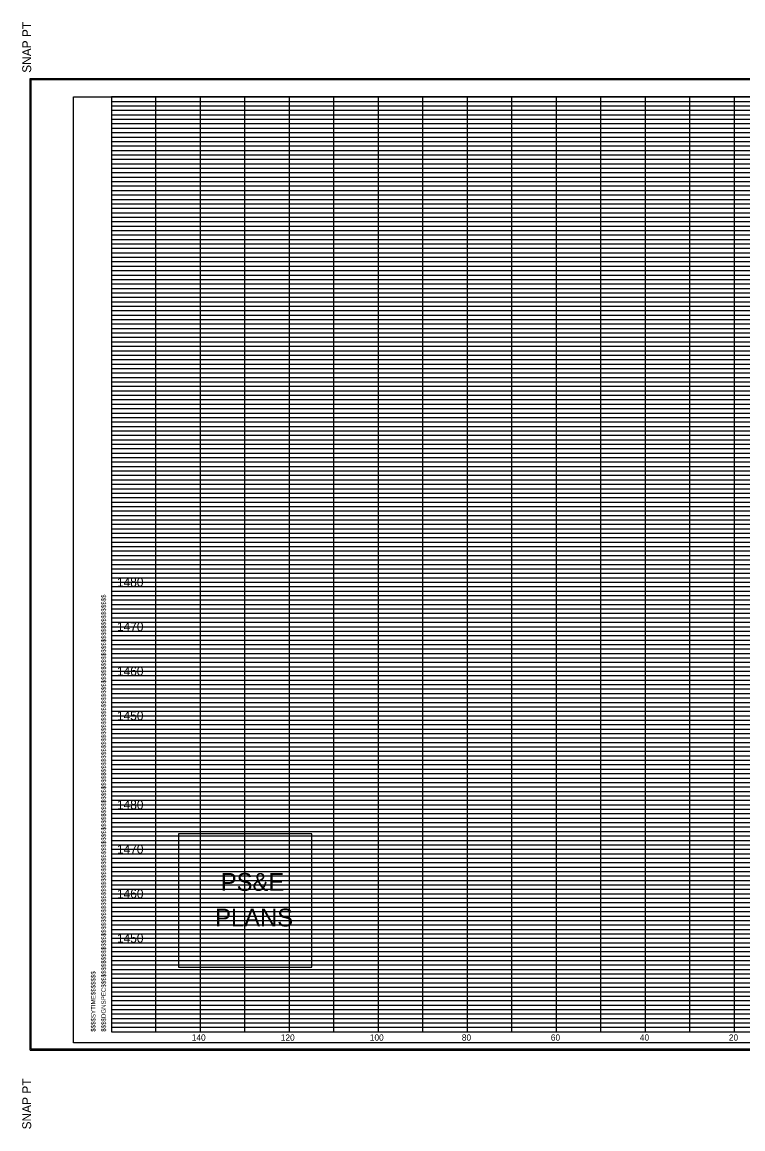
# Model space of a CAD drawing. Extents: x 980 to 1324, y 978 to 1227.
# Drawn here: x 979.9 to 1141.9, y 978.2 to 1226.8 of the extents above; entities that cross this region are included whole.
import ezdxf

# ---------------------------------------------------------------- set-up
doc = ezdxf.new("R2010")
doc.units = 0
for name, color, linetype in [('DESIGN - SHEET - Corner Text', 7, 'Continuous'), ('DESIGN - SHEET - Light Grid', 7, 'Continuous'), ('DESIGN - SHEET - Linework', 7, 'Continuous'), ('DESIGN - SHEET - Plot Shape', 7, 'Continuous'), ('DESIGN - TYPICAL - Finished Grade and Subgrade', 7, 'Continuous')]:
    doc.layers.add(name, color=color, linetype=linetype)

# ---------------------------------------------------------------- blocks, each defined once
blk = doc.blocks.new('XSTSHT')
at = {"layer": 'DESIGN - SHEET - Light Grid'}
for p, q in [((0, 20.9), (8, 20.9)), ((8, 20.9), (16, 20.9)), ((0, 20.8), (8, 20.8)), ((0, 20.7), (8, 20.7)), ((8, 20.8), (16, 20.8)), ((8, 20.7), (16, 20.7)), ((0, 20.6), (8, 20.6)), ((0, 20.5), (8, 20.5)), ((0, 20.4), (8, 20.4)), ((8, 20.6), (16, 20.6)), ((8, 20.5), (16, 20.5)), ((8, 20.4), (16, 20.4)), ((0, 20.3), (8, 20.3)), ((0, 20.2), (8, 20.2)), ((8, 20.3), (16, 20.3)), ((8, 20.2), (16, 20.2)), ((0, 20.1), (8, 20.1)), ((0, 19.9), (8, 19.9)), ((8, 20.1), (16, 20.1)), ((8, 19.9), (16, 19.9)), ((0, 19.8), (8, 19.8)), ((0, 19.7), (8, 19.7)), ((8, 19.8), (16, 19.8)), ((8, 19.7), (16, 19.7)), ((0, 19.6), (8, 19.6)), ((0, 19.5), (8, 19.5)), ((0, 19.4), (8, 19.4)), ((8, 19.6), (16, 19.6)), ((8, 19.5), (16, 19.5)), ((8, 19.4), (16, 19.4)), ((0, 19.3), (8, 19.3)), ((0, 19.2), (8, 19.2)), ((8, 19.3), (16, 19.3)), ((8, 19.2), (16, 19.2)), ((0, 19.1), (8, 19.1)), ((0, 18.9), (8, 18.9)), ((8, 19.1), (16, 19.1)), ((8, 18.9), (16, 18.9)), ((0, 18.8), (8, 18.8)), ((0, 18.7), (8, 18.7)), ((8, 18.8), (16, 18.8)), ((8, 18.7), (16, 18.7)), ((0, 18.6), (8, 18.6)), ((0, 18.5), (8, 18.5)), ((0, 18.4), (8, 18.4)), ((8, 18.6), (16, 18.6)), ((8, 18.5), (16, 18.5)), ((8, 18.4), (16, 18.4)), ((0, 18.3), (8, 18.3)), ((0, 18.2), (8, 18.2)), ((8, 18.3), (16, 18.3)), ((8, 18.2), (16, 18.2)), ((0, 18.1), (8, 18.1)), ((8, 18.1), (16, 18.1)), ((0, 17.9), (8, 17.9)), ((0, 17.8), (8, 17.8)), ((0, 17.7), (8, 17.7)), ((8, 17.9), (16, 17.9)), ((8, 17.8), (16, 17.8)), ((8, 17.7), (16, 17.7)), ((0, 17.6), (8, 17.6)), ((0, 17.5), (8, 17.5)), ((8, 17.6), (16, 17.6)), ((8, 17.5), (16, 17.5)), ((0, 17.4), (8, 17.4)), ((0, 17.3), (8, 17.3)), ((0, 17.2), (8, 17.2)), ((8, 17.4), (16, 17.4)), ((8, 17.3), (16, 17.3)), ((8, 17.2), (16, 17.2)), ((0, 17.1), (8, 17.1)), ((8, 17.1), (16, 17.1)), ((0, 16.9), (8, 16.9)), ((0, 16.8), (8, 16.8)), ((0, 16.7), (8, 16.7)), ((8, 16.9), (16, 16.9)), ((8, 16.8), (16, 16.8)), ((8, 16.7), (16, 16.7)), ((0, 16.6), (8, 16.6)), ((0, 16.5), (8, 16.5)), ((8, 16.6), (16, 16.6)), ((8, 16.5), (16, 16.5)), ((0, 16.4), (8, 16.4)), ((0, 16.3), (8, 16.3)), ((0, 16.2), (8, 16.2)), ((8, 16.4), (16, 16.4)), ((8, 16.3), (16, 16.3)), ((8, 16.2), (16, 16.2)), ((0, 16.1), (8, 16.1)), ((8, 16.1), (16, 16.1)), ((0, 15.9), (8, 15.9)), ((0, 15.8), (8, 15.8)), ((0, 15.7), (8, 15.7)), ((8, 15.9), (16, 15.9)), ((8, 15.8), (16, 15.8)), ((8, 15.7), (16, 15.7)), ((0, 15.6), (8, 15.6)), ((0, 15.5), (8, 15.5)), ((8, 15.6), (16, 15.6)), ((8, 15.5), (16, 15.5)), ((0, 15.4), (8, 15.4)), ((0, 15.3), (8, 15.3)), ((0, 15.2), (8, 15.2)), ((8, 15.4), (16, 15.4)), ((8, 15.3), (16, 15.3)), ((8, 15.2), (16, 15.2)), ((0, 15.1), (8, 15.1)), ((8, 15.1), (16, 15.1)), ((0, 14.9), (8, 14.9)), ((0, 14.8), (8, 14.8)), ((0, 14.7), (8, 14.7)), ((8, 14.9), (16, 14.9)), ((8, 14.8), (16, 14.8)), ((8, 14.7), (16, 14.7)), ((0, 14.6), (8, 14.6)), ((0, 14.5), (8, 14.5)), ((8, 14.6), (16, 14.6)), ((8, 14.5), (16, 14.5)), ((0, 14.4), (8, 14.4)), ((0, 14.3), (8, 14.3)), ((0, 14.2), (8, 14.2)), ((8, 14.4), (16, 14.4)), ((8, 14.3), (16, 14.3)), ((8, 14.2), (16, 14.2)), ((0, 14.1), (8, 14.1)), ((8, 14.1), (16, 14.1)), ((0, 13.9), (8, 13.9)), ((0, 13.8), (8, 13.8)), ((0, 13.7), (8, 13.7)), ((8, 13.9), (16, 13.9)), ((8, 13.8), (16, 13.8)), ((8, 13.7), (16, 13.7)), ((0, 13.6), (8, 13.6)), ((0, 13.5), (8, 13.5)), ((8, 13.6), (16, 13.6)), ((8, 13.5), (16, 13.5)), ((0, 13.4), (8, 13.4)), ((0, 13.3), (8, 13.3)), ((0, 13.2), (8, 13.2)), ((8, 13.4), (16, 13.4)), ((8, 13.3), (16, 13.3)), ((8, 13.2), (16, 13.2)), ((0, 13.1), (8, 13.1)), ((8, 13.1), (16, 13.1)), ((0, 12.9), (8, 12.9)), ((0, 12.8), (8, 12.8)), ((0, 12.7), (8, 12.7)), ((8, 12.9), (16, 12.9)), ((8, 12.8), (16, 12.8)), ((8, 12.7), (16, 12.7)), ((0, 12.6), (8, 12.6)), ((0, 12.5), (8, 12.5)), ((8, 12.6), (16, 12.6)), ((8, 12.5), (16, 12.5)), ((0, 12.4), (8, 12.4)), ((0, 12.3), (8, 12.3)), ((0, 12.2), (8, 12.2)), ((8, 12.4), (16, 12.4)), ((8, 12.3), (16, 12.3)), ((8, 12.2), (16, 12.2)), ((0, 12.1), (8, 12.1)), ((8, 12.1), (16, 12.1)), ((0, 11.9), (8, 11.9)), ((0, 11.8), (8, 11.8)), ((0, 11.7), (8, 11.7)), ((8, 11.9), (16, 11.9)), ((8, 11.8), (16, 11.8)), ((8, 11.7), (16, 11.7)), ((0, 11.6), (8, 11.6)), ((0, 11.5), (8, 11.5)), ((8, 11.6), (16, 11.6)), ((8, 11.5), (16, 11.5)), ((0, 11.4), (8, 11.4)), ((0, 11.3), (8, 11.3)), ((0, 11.2), (8, 11.2)), ((8, 11.4), (16, 11.4)), ((8, 11.3), (16, 11.3)), ((8, 11.2), (16, 11.2)), ((0, 11.1), (8, 11.1)), ((8, 11.1), (16, 11.1)), ((0, 10.9), (8, 10.9)), ((0, 10.8), (8, 10.8)), ((0, 10.7), (8, 10.7)), ((8, 10.9), (16, 10.9)), ((8, 10.8), (16, 10.8)), ((8, 10.7), (16, 10.7)), ((0, 10.6), (8, 10.6)), ((0, 10.5), (8, 10.5)), ((8, 10.6), (16, 10.6)), ((8, 10.5), (16, 10.5)), ((0, 10.4), (8, 10.4)), ((0, 10.3), (8, 10.3)), ((0, 10.2), (8, 10.2)), ((8, 10.4), (16, 10.4)), ((8, 10.3), (16, 10.3)), ((8, 10.2), (16, 10.2)), ((0, 10.1), (8, 10.1)), ((8, 10.1), (16, 10.1)), ((0, 9.9), (8, 9.9)), ((0, 9.8), (8, 9.8)), ((0, 9.7), (8, 9.7)), ((8, 9.9), (16, 9.9)), ((8, 9.8), (16, 9.8)), ((8, 9.7), (16, 9.7)), ((0, 9.6), (8, 9.6)), ((0, 9.5), (8, 9.5)), ((8, 9.6), (16, 9.6)), ((8, 9.5), (16, 9.5)), ((0, 9.4), (8, 9.4)), ((0, 9.3), (8, 9.3)), ((0, 9.2), (8, 9.2)), ((8, 9.4), (16, 9.4)), ((8, 9.3), (16, 9.3)), ((8, 9.2), (16, 9.2)), ((0, 9.1), (8, 9.1)), ((8, 9.1), (16, 9.1)), ((0, 8.9), (8, 8.9)), ((0, 8.8), (8, 8.8)), ((8, 8.9), (16, 8.9)), ((8, 8.8), (16, 8.8)), ((0, 8.7), (8, 8.7)), ((0, 8.6), (8, 8.6)), ((0, 8.5), (8, 8.5)), ((8, 8.7), (16, 8.7)), ((8, 8.6), (16, 8.6)), ((8, 8.5), (16, 8.5)), ((0, 8.4), (8, 8.4)), ((0, 8.3), (8, 8.3)), ((8, 8.4), (16, 8.4)), ((8, 8.3), (16, 8.3)), ((0, 8.2), (8, 8.2)), ((0, 8.1), (8, 8.1)), ((8, 8.2), (16, 8.2)), ((8, 8.1), (16, 8.1)), ((0, 7.9), (8, 7.9)), ((0, 7.8), (8, 7.8)), ((8, 7.9), (16, 7.9)), ((8, 7.8), (16, 7.8)), ((0, 7.7), (8, 7.7)), ((0, 7.6), (8, 7.6)), ((0, 7.5), (8, 7.5)), ((8, 7.7), (16, 7.7)), ((8, 7.6), (16, 7.6)), ((8, 7.5), (16, 7.5)), ((0, 7.4), (8, 7.4)), ((0, 7.3), (8, 7.3)), ((8, 7.4), (16, 7.4)), ((8, 7.3), (16, 7.3)), ((0, 7.2), (8, 7.2)), ((0, 7.1), (8, 7.1)), ((8, 7.2), (16, 7.2)), ((8, 7.1), (16, 7.1)), ((0, 6.9), (8, 6.9)), ((0, 6.8), (8, 6.8)), ((8, 6.9), (16, 6.9)), ((8, 6.8), (16, 6.8)), ((0, 6.7), (8, 6.7)), ((0, 6.6), (8, 6.6)), ((0, 6.5), (8, 6.5)), ((8, 6.7), (16, 6.7)), ((8, 6.6), (16, 6.6)), ((8, 6.5), (16, 6.5)), ((0, 6.4), (8, 6.4)), ((0, 6.3), (8, 6.3)), ((8, 6.4), (16, 6.4)), ((8, 6.3), (16, 6.3)), ((0, 6.2), (8, 6.2)), ((0, 6.1), (8, 6.1)), ((8, 6.2), (16, 6.2)), ((8, 6.1), (16, 6.1)), ((0, 5.9), (8, 5.9)), ((0, 5.8), (8, 5.8)), ((8, 5.9), (16, 5.9)), ((8, 5.8), (16, 5.8)), ((0, 5.7), (8, 5.7)), ((0, 5.6), (8, 5.6)), ((0, 5.5), (8, 5.5)), ((8, 5.7), (16, 5.7)), ((8, 5.6), (16, 5.6)), ((8, 5.5), (16, 5.5)), ((0, 5.4), (8, 5.4)), ((0, 5.3), (8, 5.3)), ((8, 5.4), (16, 5.4)), ((8, 5.3), (16, 5.3)), ((0, 5.2), (8, 5.2)), ((0, 5.1), (8, 5.1)), ((8, 5.2), (16, 5.2)), ((8, 5.1), (16, 5.1)), ((0, 4.9), (8, 4.9)), ((0, 4.8), (8, 4.8)), ((8, 4.9), (16, 4.9)), ((8, 4.8), (16, 4.8)), ((0, 4.7), (8, 4.7)), ((0, 4.6), (8, 4.6)), ((0, 4.5), (8, 4.5)), ((8, 4.7), (16, 4.7)), ((8, 4.6), (16, 4.6)), ((8, 4.5), (16, 4.5)), ((0, 4.4), (8, 4.4)), ((0, 4.3), (8, 4.3)), ((8, 4.4), (16, 4.4)), ((8, 4.3), (16, 4.3)), ((0, 4.2), (8, 4.2)), ((0, 4.1), (8, 4.1)), ((8, 4.2), (16, 4.2)), ((8, 4.1), (16, 4.1)), ((0, 3.9), (8, 3.9)), ((0, 3.8), (8, 3.8)), ((8, 3.9), (16, 3.9)), ((8, 3.8), (16, 3.8)), ((0, 3.7), (8, 3.7)), ((0, 3.6), (8, 3.6)), ((0, 3.5), (8, 3.5)), ((8, 3.7), (16, 3.7)), ((8, 3.6), (16, 3.6)), ((8, 3.5), (16, 3.5)), ((0, 3.4), (8, 3.4)), ((0, 3.3), (8, 3.3)), ((8, 3.4), (16, 3.4)), ((8, 3.3), (16, 3.3)), ((0, 3.2), (8, 3.2)), ((0, 3.1), (8, 3.1)), ((8, 3.2), (16, 3.2)), ((8, 3.1), (16, 3.1)), ((0, 2.9), (8, 2.9)), ((0, 2.8), (8, 2.8)), ((8, 2.9), (16, 2.9)), ((8, 2.8), (16, 2.8)), ((0, 2.7), (8, 2.7)), ((0, 2.6), (8, 2.6)), ((0, 2.5), (8, 2.5)), ((8, 2.7), (16, 2.7)), ((8, 2.6), (16, 2.6)), ((8, 2.5), (16, 2.5)), ((0, 2.4), (8, 2.4)), ((0, 2.3), (8, 2.3)), ((8, 2.4), (16, 2.4)), ((8, 2.3), (16, 2.3)), ((0, 2.2), (8, 2.2)), ((0, 2.1), (8, 2.1)), ((8, 2.2), (16, 2.2)), ((8, 2.1), (16, 2.1)), ((0, 1.9), (8, 1.9)), ((0, 1.8), (8, 1.8)), ((8, 1.9), (16, 1.9)), ((8, 1.8), (16, 1.8)), ((0, 1.7), (8, 1.7)), ((0, 1.6), (8, 1.6)), ((0, 1.5), (8, 1.5)), ((8, 1.7), (16, 1.7)), ((8, 1.6), (16, 1.6)), ((8, 1.5), (16, 1.5)), ((0, 1.4), (8, 1.4)), ((0, 1.3), (8, 1.3)), ((8, 1.4), (16, 1.4)), ((8, 1.3), (16, 1.3)), ((0, 1.2), (8, 1.2)), ((0, 1.1), (8, 1.1)), ((8, 1.2), (16, 1.2)), ((8, 1.1), (16, 1.1)), ((0, 0.9), (8, 0.9)), ((0, 0.8), (8, 0.8)), ((8, 0.9), (16, 0.9)), ((8, 0.8), (16, 0.8)), ((0, 0.7), (8, 0.7)), ((0, 0.6), (8, 0.6)), ((0, 0.5), (8, 0.5)), ((8, 0.7), (16, 0.7)), ((8, 0.6), (16, 0.6)), ((8, 0.5), (16, 0.5)), ((0, 0.4), (8, 0.4)), ((0, 0.3), (8, 0.3)), ((8, 0.4), (16, 0.4)), ((8, 0.3), (16, 0.3)), ((0, 0.2), (8, 0.2)), ((0, 0.1), (8, 0.1)), ((8, 0.2), (16, 0.2)), ((8, 0.1), (16, 0.1))]:
    blk.add_line(p, q, dxfattribs=at)
at = {"layer": 'DESIGN - SHEET - Linework'}
for p, q in [((-1.823, -0.414), (-1.823, 21.414)), ((-1.823, 21.414), (32.217, 21.414)), ((1, 0), (1, 21)), ((2, 0), (2, 21)), ((3, 0), (3, 21)), ((4, 0), (4, 21)), ((5, 0), (5, 21)), ((6, 0), (6, 21)), ((7, 0), (7, 21)), ((8, 0), (8, 21)), ((9, 0), (9, 21)), ((10, 0), (10, 21)), ((11, 0), (11, 21)), ((12, 0), (12, 21)), ((13, 0), (13, 21)), ((14, 0), (14, 21)), ((0, 20), (28, 20)), ((0, 19), (32, 19)), ((0, 18), (32, 18)), ((0, 17), (32, 17)), ((0, 16), (32, 16)), ((0, 15), (32, 15)), ((0, 14), (32, 14)), ((0, 13), (32, 13)), ((0, 12), (32, 12)), ((0, 11), (32, 11)), ((0, 10), (32, 10)), ((0, 9), (32, 9)), ((0, 8), (32, 8)), ((0, 7), (32, 7)), ((0, 6), (32, 6)), ((0, 5), (32, 5)), ((0, 4), (32, 4)), ((0, 3), (32, 3)), ((0, 2), (32, 2)), ((0, 1), (32, 1)), ((-1.823, -0.414), (32.217, -0.414))]:
    blk.add_line(p, q, dxfattribs=at)
blk.add_lwpolyline([(0, 21), (0, 0), (32, 0), (32, 21), (0, 21)], dxfattribs=at)
at = {"layer": 'DESIGN - SHEET - Plot Shape'}
for points in [[(-1.803, 21.394), (32.197, 21.394), (32.197, -0.394), (-1.803, -0.394)], [(-0.85, 21), (32, 21), (32, -0.25), (-0.85, -0.25)]]:
    blk.add_lwpolyline(points, close=True, dxfattribs=at)
at = {"layer": 'DESIGN - SHEET - Corner Text'}
for s, height, p in [('  SNAP PT', 0.2, (-1.803, 21.394)), ('$$$$DGNSPEC$$$$$$$$$$$$$$$$$$$$$$$$$$$$$$$$$$$$$$$$$$$$$$$$$$$$$$$$$$$$$$$$$$$$$$$$$$$$$$$$$$$$$$$$$$$$$$$$$$$$$$$$$$$$$$$$$$$', 0.100002, (-0.126, 0)), ('$$$$SYTIME$$$$$$$', 0.1, (-0.358, 0)), ('SNAP PT  ', 0.2, (-1.803, -2.194))]:
    blk.add_text(s, height=height, rotation=90, dxfattribs=at).set_placement(p)

msp = doc.modelspace()

# ---------------------------------------------------------------- linework, layer by layer
at = {"layer": 'DESIGN - SHEET - Corner Text'}
msp.add_lwpolyline([(1015.05, 1044.49), (1015.05, 1014.49), (1045.05, 1014.49), (1045.05, 1044.49)], close=True, dxfattribs=at)

# ---------------------------------------------------------------- block references
at = {"layer": 'DESIGN - TYPICAL - Finished Grade and Subgrade', "xscale": 10, "yscale": 10}
msp.add_blockref('XSTSHT', (1000, 1000), dxfattribs=at)

# ---------------------------------------------------------------- texts
at = {"layer": 'DESIGN - SHEET - Corner Text'}
for s, height, p in [('1480', 2, (1001.25, 1100)), ('1470', 2, (1001.25, 1090)), ('1460', 2, (1001.25, 1080)), ('1450', 2, (1001.25, 1070)), ('1480', 2, (1001.25, 1050)), ('1470', 2, (1001.25, 1040)), ('PS&E', 4, (1024.57, 1031.66)), ('1460', 2, (1001.25, 1030)), ('PLANS', 4, (1023.29, 1023.66)), ('1450', 2, (1001.25, 1020)), ('140', 1.4, (1018.06, 998)), ('120', 1.4, (1038.06, 998)), ('100', 1.4, (1058.06, 998)), ('80', 1.4, (1078.74, 998)), ('60', 1.4, (1098.74, 998)), ('40', 1.4, (1118.74, 998)), ('20', 1.4, (1138.74, 998))]:
    msp.add_text(s, height=height, dxfattribs=at).set_placement(p)

doc.saveas('drawing.dxf')
